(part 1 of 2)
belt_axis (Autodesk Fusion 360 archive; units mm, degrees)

design "assy_belt_axis" references "belt_idler", "HW_M5x40-FHCS", "HW_M3x50-SHCS", "carriage_front_generic", "circuit_mount_stepper_simple", "belt_motor_mount", "HW_M3-Washer", "FRM-Extrusion-VSlot-2020-350", "HW_M5x10-FHCS", "HW_M3x8-SHCS", "limit_mount", "HW_M3x16-SHCS", "lil_foot", "belt_clip"
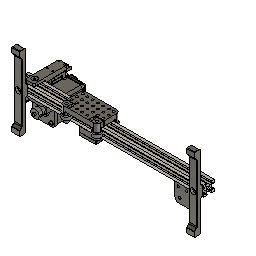
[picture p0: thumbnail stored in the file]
component_insert "Component Insert1"
joint "Assemble1" alignAngle -90 alignOffsetX 0 alignOffsetY 0 alignOffsetZ -6
component_insert "Component Insert2"
joint "Assemble2" alignAngle 0 alignOffsetX 0 alignOffsetY 0 alignOffsetZ -10
component_insert "Component Insert3"
joint "Assemble3" alignAngle 90 alignOffsetX 0 alignOffsetY 0 alignOffsetZ 0
component_insert "Component Insert4"
joint "Assemble4" alignAngle 0 alignOffsetX 0 alignOffsetY 25 alignOffsetZ 6
component_insert "Component Insert5"
joint "Assemble5" alignAngle 180 alignOffsetX 0 alignOffsetY -22 alignOffsetZ 6
component_insert "Component Insert6"
joint "Assemble6" alignAngle 270 alignOffsetX 0 alignOffsetY 21 alignOffsetZ 6
component_insert "Component Insert7"
joint "Assemble7" alignAngle 0 alignOffsetX 0 alignOffsetY 10 alignOffsetZ 6
component_insert "Component Insert8"
joint "Assemble8" alignAngle 0 alignOffsetX 0 alignOffsetY -10 alignOffsetZ 6
component_insert "Component Insert9"
joint "Assemble9" alignAngle 90 alignOffsetX 0 alignOffsetY 0 alignOffsetZ 0
component_insert "Component Insert10"
joint "Assemble10" alignAngle 180 alignOffsetX 0 alignOffsetY 0 alignOffsetZ 0
component_insert "Component Insert11"
component_insert "Component Insert12"
component_insert "Component Insert13"
component_insert "Component Insert14"
component_insert "Component Insert15"
component_insert "Component Insert16"
component_insert "Component Insert17"
component_insert "Component Insert18"
joint "Assemble11" alignAngle 90 alignOffsetX 0 alignOffsetY 0 alignOffsetZ 0
joint "Assemble12" alignAngle 90 alignOffsetX 0 alignOffsetY 0 alignOffsetZ 0
joint "Assemble13" alignAngle -90 alignOffsetX 0 alignOffsetY 0 alignOffsetZ 0
joint "Assemble14" alignAngle 90 alignOffsetX 0 alignOffsetY 0 alignOffsetZ 0
joint "Assemble15" alignAngle -90 alignOffsetX 0 alignOffsetY 0 alignOffsetZ 0
joint "Assemble16" alignAngle -90 alignOffsetX 0 alignOffsetY 0 alignOffsetZ 0
joint "Assemble17" alignAngle 90 alignOffsetX 0 alignOffsetY 0 alignOffsetZ 0
joint "Assemble18" alignAngle 90 alignOffsetX 0 alignOffsetY 0 alignOffsetZ 0
component_insert "Component Insert19"
component_insert "Component Insert20"
joint "Assemble19" alignAngle 90 alignOffsetX 0 alignOffsetY 0 alignOffsetZ 0
joint "Assemble20" alignAngle -90 alignOffsetX 0 alignOffsetY 0 alignOffsetZ 0
component_insert "Component Insert21"
component_insert "Component Insert22"
joint "Assemble21" alignAngle -90 alignOffsetX 0 alignOffsetY 0 alignOffsetZ 0
joint "Assemble22" alignAngle -90 alignOffsetX 0 alignOffsetY 0 alignOffsetZ 0
component_insert "Component Insert23"
joint "Assemble23" alignAngle 180 alignOffsetX 0 alignOffsetY 0 alignOffsetZ 0
component_insert "Component Insert24"
component_insert "Component Insert25"
component_insert "Component Insert26"
component_insert "Component Insert27"
component_insert "Component Insert28"
component_insert "Component Insert29"
component_insert "Component Insert30"
component_insert "Component Insert31"
joint "Assemble24" alignAngle 90 alignOffsetX 0 alignOffsetY 0 alignOffsetZ 0
joint "Assemble25" alignAngle 90 alignOffsetX 0 alignOffsetY 0 alignOffsetZ 0
joint "Assemble26" alignAngle 90 alignOffsetX 0 alignOffsetY 0 alignOffsetZ 0
joint "Assemble27" alignAngle 90 alignOffsetX 0 alignOffsetY 0 alignOffsetZ 0
joint "Assemble28" alignAngle 0 alignOffsetX 0 alignOffsetY 0 alignOffsetZ 0
joint "Assemble29" alignAngle 0 alignOffsetX 0 alignOffsetY 0 alignOffsetZ 0
joint "Assemble30" alignAngle 0 alignOffsetX 0 alignOffsetY 0 alignOffsetZ 0
joint "Assemble31" alignAngle 0 alignOffsetX 0 alignOffsetY 0 alignOffsetZ 0
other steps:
joint_origin "JointOrigin1"
joint_origin "JointOrigin2"

design "PP_TRNS_Mini-V-Wheel"
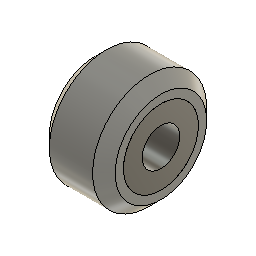
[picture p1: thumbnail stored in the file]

design "PP_BRNG_625F-5x16x5"
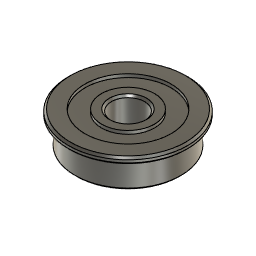
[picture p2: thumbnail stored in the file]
sketch "Sketch1" plane through (0, 0, 0) normal (0, 1, 0) x axis (1, 0, 0)
  line L1 (4, -2.5) -> (2.5, -2.5)
  line L2 (2.5, 2.5) -> (4, 2.5)
  line L3 (2.5, -2.5) -> (2.5, 2.5)
  line L4 (8, -2.5) -> (6.5, -2.5)
  line L5 (8, 2.5) -> (8, -2.5)
  line L6 (6.5, 2.5) -> (8, 2.5)
  line L7 (6.5, -2) -> (4, -2)
  line L8 (6.5, 2) -> (4, 2)
  line L9 (4, -2) -> (4, -2.5)
  line L10 (4, 2.5) -> (4, 2)
  line L11 (6.5, 2) -> (6.5, 2.5)
  line L12 (6.5, -2.5) -> (6.5, -2)
  line L13 (0, 0) -> (8, 0)
  line L14 (9, -2.5) -> (8, -2.5)
  line L15 (9, -1.5) -> (9, -2.5)
  line L16 (8, -1.5) -> (9, -1.5)
  point P11 (6.5, -2)
  point P12 (4, 2)
  point P14 (8, 0)
  point P1 (0, 0)
  point P15 (0, 0)
  point P16 (2.5, 0)
  point P6 (6.5, -2.5)
  point P19 (8, -1.5)
  point P3 (4, -2.5)
  point P10 (4, -2)
  point P7 (8, -2.5)
  point P8 (8, 2.5)
  point P2 (2.5, -2.5)
  point P17 (9, -2.5)
  point P18 (9, -1.5)
  horizontal L1
  vertical L9
  horizontal L2
  vertical L3
  horizontal L4
  vertical L5
  horizontal L6
  vertical L11
  coincident P11 L11
  perpendicular L7 L11
  coincident P12 L9
  perpendicular L8 L9
  collinear L9 L10
  collinear L11 L12
  midpoint L5 P14
  coincident P1 P15
  horizontal L13
  midpoint L3 P16
  coincident L13 P16
  equal L1 L4
  equal L9 L10
  coincident L1 P6
  perpendicular L5 L14
  perpendicular L4 L15
  coincident L5 P19
  perpendicular L5 L16
  dimension "d1" distance P1 L3 = 2.5 (= "( 5 / 2 ) * 1 mm")
  dimension "d2" distance P1 L5 = 8 (= "( 16 / 2 ) * 1 mm")
  dimension "d4" distance P3 P10 = 0.5
  dimension "d5" distance P7 P8 = 5
  dimension "d8" distance P2 P3 = 1.5
  dimension "d9" distance P17 P18 = 1
  dimension "d10" distance P1 P17 = 9 (= "( 18 / 2 ) * 1 mm")
revolve "Revolve1" sketch "Sketch1" AlongAngle 360
chamfer "Chamfer1" distance 0.3

design "HW_M5x10-FHCS"
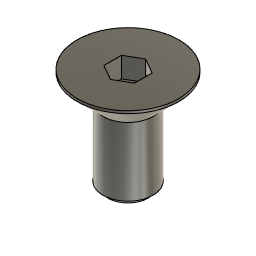
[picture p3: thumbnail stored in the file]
sketch "Sketch1" plane through (0, 0, 0) normal (0, 1, 0) x axis (1, 0, 0)
  line L1 (0, 10) -> (0, 0)
  line L2 (1.95, 10) -> (0, 10)
  line L3 (2.45, 9.5) -> (1.95, 10)
  line L4 (2.45, 2.8) -> (2.45, 9.5)
  line L5 (5, 0.25) -> (2.45, 2.8)
  line L6 (5, 0) -> (5, 0.25)
  line L7 (0, 0) -> (5, 0)
  point P1 (0, 0)
  point P2 (0, 0)
  point P9 (0, 0)
  point P3 (0, 10)
  point P4 (1.95, 10)
  point P8 (5, 0)
  point P7 (5, 0.25)
  coincident P1 P2
  vertical L1
  perpendicular L1 L2
  perpendicular L2 L4
  parallel L3 L5
  parallel L4 L6
  perpendicular L6 L7
  coincident P1 P9
  dimension "d1" distance P3 L4 = 2.45 (= "( 4.9 / 2 ) * 1 mm")
  dimension "d3" angle L2 L3 = 45
  dimension "d5" distance P4 L4 = 0.5
  dimension "d6" distance P2 P3 = 10
  dimension "d7" distance P8 P9 = 5 (= "( 10 / 2 ) * 1 mm")
  dimension "d9" distance P7 P8 = 0.25
revolve "Revolve1" sketch "Sketch1" AlongAngle 360
sketch "Sketch2" plane through (0, 0, 0) normal (0, 0, 1) x axis (-1, 0, 0)
  line L1 (0, -1.7321) -> (-1.5, -0.866)
  line L2 (1.5, -0.866) -> (0, -1.7321)
  line L3 (1.5, 0.866) -> (1.5, -0.866)
  line L4 (0, 1.7321) -> (1.5, 0.866)
  line L5 (-1.5, 0.866) -> (0, 1.7321)
  line L6 (-1.5, -0.866) -> (-1.5, 0.866)
  circle C1 centre (0, 0) radius 5
  point P1 (0, 0)
  point P9 (0, 0)
  coincident P1 P9
  vertical L6
  dimension "d12" distance L3 L6 = 3
extrude "Extrude1" cut sketch "Sketch2" profile of L1 L2 L3 L4 L5 L6 against normal blind 2

design "lil_foot"
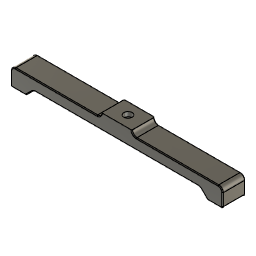
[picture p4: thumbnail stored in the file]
sketch "Sketch1" plane through (0, 0, 0) normal (0, 1, 0) x axis (1, 0, 0)
  line L1 (0, 0) -> (-10, 0)
  line L2 (-10, 3) -> (-10, 0)
  line L3 (-70, 3) -> (-10, 3)
  line L4 (-70, 15) -> (-70, 3)
  line L5 (-60, 15) -> (-70, 15)
  line L6 (-55, 10) -> (-60, 15)
  line L7 (0, 10) -> (-55, 10)
  line L8 (0, 0) -> (0, 10)
  line L9 (0, 0) -> (10, 0)
  line L10 (10, 3) -> (10, 0)
  line L11 (70, 3) -> (10, 3)
  line L12 (70, 15) -> (70, 3)
  line L13 (60, 15) -> (70, 15)
  line L14 (55, 10) -> (60, 15)
  line L15 (0, 10) -> (55, 10)
  point P1 (0, 0)
  point P9 (0, 0)
  point P10 (0, 0)
  point P2 (-10, 0)
  point P11 (10, 0)
  point P3 (-10, 3)
  point P13 (10, 3)
  point P4 (-70, 3)
  point P14 (70, 3)
  point P5 (-70, 15)
  point P15 (70, 15)
  point P6 (-60, 15)
  point P16 (60, 15)
  point P7 (-55, 10)
  point P17 (55, 10)
  point P8 (0, 10)
  point P18 (0, 10)
  point P12 (0, 0)
  horizontal L1
  perpendicular L1 L2
  perpendicular L2 L3
  perpendicular L3 L4
  perpendicular L4 L5
  perpendicular L4 L7
  perpendicular L7 L8
  coincident P1 P9
  coincident L8 P10
  coincident P1 P10
  symmetric P2 L8 P11
  symmetric P3 L8 P13
  symmetric P4 L8 P14
  symmetric P5 L8 P15
  symmetric P6 L8 P16
  symmetric P7 L8 P17
  symmetric P8 L8 P18
  symmetric L8 P10 P12
  dimension "d2" distance P2 P10 = 10
  dimension "d4" angle L6 L7 = 45
  dimension "d5" distance P5 P6 = 10
  dimension "d6" distance P6 P7 = 5
  dimension "d8" distance P5 P8 = 70 (= "( 140 / 2 ) * 1 mm")
  dimension "d9" distance P2 P3 = 3
  dimension "d11" distance P2 P5 = 15
  dimension "d12" distance P1 P8 = 10
extrude "Extrude1" new body sketch "Sketch1" profile of L1 L2 L3 L4 L5 L6 L7 L9 L10 L11 L12 L13 L14 L15 along normal blind 15
sketch "Sketch2" plane through (0, 0, 0) normal (0, 0, 1) x axis (-1, 0, 0)
  line L1 (-10, 0) -> (10, 0)
  line L2 (-10, -15) -> (-10, 0)
  line L3 (10, -15) -> (-10, -15)
  line L4 (10, 0) -> (10, -15)
  line L5 (0, -15) -> (0, 0)
  circle C1 centre (0, -7.5) radius 2.75
  circle C2 centre (0, -7.5) radius 5.25
  point P1 (0, 0)
  point P6 (0, 0)
  point P7 (0, -15)
  point P8 (0, -7.5)
  coincident P1 P6
  midpoint L3 P7
  midpoint L5 P8
  concentric C1 C2
  dimension "d15" diameter C2 = 10.5
  dimension "d16" diameter C1 = 5.5
extrude "Extrude2" cut sketch "Sketch2" profile of C1 to an object
extrude "Extrude3" cut sketch "Sketch2" profile of L2 L4 C1 C2 no distance stored from offset -5.5
chamfer "Chamfer1" distance 2.5
fillet "Fillet1" radius 3
fillet "Fillet2" radius 1
chamfer "Chamfer2" distance 0.5
named bodies: "lil_foot"

design "HW_M5-Washer"
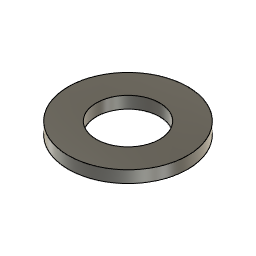
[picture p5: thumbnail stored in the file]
sketch "Sketch1" plane through (0, 0, 0) normal (0, 1, 0) x axis (1, 0, 0)
  line L1 (5, 0) -> (2.65, 0)
  line L2 (5, -1) -> (5, 0)
  line L3 (2.65, -1) -> (5, -1)
  line L4 (2.65, 0) -> (2.65, -1)
  point P1 (0, 0)
  point P2 (2.65, 0)
  point P5 (2.65, -1)
  horizontal L1
  vertical L2
  horizontal L3
  vertical L4
  coincident P1 L1
  dimension "d1" distance P2 P5 = 1
  dimension "d2" distance P1 L4 = 2.65 (= "( 5.3 / 2 ) * 1 mm")
  dimension "d3" distance P1 L2 = 5 (= "( 10 / 2 ) * 1 mm")
revolve "Revolve1" sketch "Sketch1" AlongAngle 360

design "belt_motor_mount" references "PP_ACTU_N17-Stepper", "PP_TRNS_GT2-Pulley-20T-6mm"
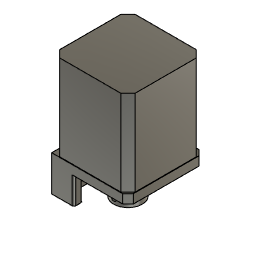
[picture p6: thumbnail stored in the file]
sketch "Sketch1" plane through (0, 0, 0) normal (0, 0, 1) x axis (1, 0, 0)
  line L1 (0.2162, 21.15) -> (42.5162, 21.15)
  line L2 (0.2162, -21.15) -> (0.2162, 21.15)
  line L3 (42.5162, -21.15) -> (0.2162, -21.15)
  line L4 (42.5162, 21.15) -> (42.5162, -21.15)
  line L5 (0.2162, -21.15) -> (42.5162, 21.15)
  line L6 (42.5162, -21.15) -> (0.2162, 21.15)
  line L7 (0, 0) -> (21.3662, 0)
  line L8 (36.8662, 15.5) -> (5.8662, 15.5)
  line L9 (36.8662, -15.5) -> (36.8662, 15.5)
  line L10 (5.8662, -15.5) -> (36.8662, -15.5)
  line L11 (5.8662, 15.5) -> (5.8662, -15.5)
  line L12 (5, -12.1089) -> (5, 12.1089)
  line L13 (12.5, -16.4) -> (9.2485, -16.4)
  line L14 (12.5, -21.4) -> (12.5, -16.4)
  line L15 (0, 21.4) -> (0, -21.4)
  line L16 (42.7662, 21.4) -> (0, 21.4)
  line L17 (42.7662, -21.4) -> (42.7662, 21.4)
  line L18 (0, -21.4) -> (42.7662, -21.4)
  line L19 (12.5, 16.4) -> (9.2485, 16.4)
  line L20 (12.5, 21.4) -> (12.5, 16.4)
  circle C1 centre (21.3662, 0) radius 6.3662
  circle C2 centre (36.8662, 15.5) radius 1.75
  circle C3 centre (36.8662, -15.5) radius 1.75
  circle C4 centre (5.8662, -15.5) radius 1.75
  circle C5 centre (5.8662, 15.5) radius 1.75
  circle C6 centre (21.3662, 0) radius 11.05
  circle C7 centre (5.8662, -15.5) radius 3.5
  circle C8 centre (5.8662, 15.5) radius 3.5
  point P6 (21.3662, 0)
  point P7 (21.3662, 0)
  point P8 (21.3662, 0)
  point P1 (0, 0)
  point P9 (0, 0)
  point P10 (15, 0)
  point P13 (36.8662, -15.5)
  point P11 (5.8662, 15.5)
  point P12 (36.8662, 15.5)
  point P19 (21.3662, 0)
  point P15 (36.8662, 15.5)
  point P16 (36.8662, -15.5)
  point P14 (5.8662, -15.5)
  point P17 (5.8662, -15.5)
  point P18 (5.8662, 15.5)
  point P20 (5, 12.1089)
  point P21 (5, -12.1089)
  point P24 (9.2485, -16.4)
  point P27 (0, -21.4)
  point P31 (0, -21.4)
  point P26 (12.5, -21.4)
  point P32 (9.2485, 16.4)
  point P34 (12.5, 21.4)
  point P25 (12.5, -16.4)
  point P2 (42.5162, 21.15)
  point P5 (42.5162, -21.15)
  point P3 (0.2162, 21.15)
  point P29 (42.7662, 21.4)
  horizontal L1
  perpendicular L1 L2
  parallel L1 L3
  parallel L2 L4
  coincident L5 P6
  coincident L6 P6
  equal L1 L2
  coincident P6 P7
  coincident P6 P8
  coincident P1 P9
  horizontal L7
  coincident C1 P10
  coincident L7 P10
  horizontal L8
  vertical L9
  horizontal L10
  vertical L11
  coincident L6 P13
  coincident L6 P11
  coincident L5 P12
  equal C4 C5
  equal C3 C5
  equal C2 C3
  coincident P6 P19
  coincident P12 P15
  coincident P13 P16
  coincident P14 P17
  coincident P11 P18
  vertical L12
  concentric C4 C7
  concentric C5 C8
  equal C7 C8
  coincident P20 C8
  coincident P21 C7
  coincident C7 P24
  parallel L3 L13
  perpendicular L3 L14
  perpendicular L1 L15
  midpoint P1 L15
  perpendicular L15 L16
  perpendicular L16 L17
  perpendicular L17 L18
  coincident P27 P31
  coincident P26 L18
  coincident C8 P32
  parallel L8 L19
  coincident L16 P34
  perpendicular L16 L20
  coincident P25 L20
  equal L14 L20
  dimension "d1" diameter C1 = 12.7324 (= "( 20 * 2 / PI ) * 1 mm")
  dimension "d2" distance P1 P10 = 15
  dimension "d3" distance P2 P5 = 42.3
  dimension "d4" diameter C2 = 3.5
  dimension "d5" diameter C6 = 22.1
  dimension "d6" distance P12 P13 = 31
  dimension "d7" distance P1 L12 = 5
  dimension "d8" diameter C8 = 7
  dimension "d9" distance P3 L16 = 0.25
  dimension "d10" distance L4 P29 = 0.25
  dimension "d11" distance P10 L14 = 2.5
  dimension "d12" distance L13 P26 = 5
extrude "Extrude1" new body sketch "Sketch1" profile of C2 C3 C4 C5 C6 L12 C7 C8 L13 L14 L15 L16 L17 L18 L19 L20 along normal blind 5 bodies "belt_motor_mount"
extrude "Extrude2" add sketch "Sketch1" profile of L12 C7 C8 L13 L14 L15 L16 L18 L19 L20 against normal blind 15
sketch "Sketch2" plane through (0, 0, 0) normal (-1, 0, 0) x axis (0, -1, 0)
  line L1 (21.4, 5) -> (21.4, -15)
  line L2 (-21.4, 5) -> (21.4, 5)
  line L3 (-21.4, -15) -> (-21.4, 5)
  line L4 (21.4, -15) -> (-21.4, -15)
  line L5 (-21.4, -5) -> (21.4, -5)
  circle C1 centre (-7.4, -5) radius 2.75
  circle C2 centre (-7.4, -5) radius 5
  circle C3 centre (7.4, -5) radius 2.75
  circle C4 centre (7.4, -5) radius 5
  point P6 (21.4, -5)
  point P7 (-21.4, -5)
  point P8 (-7.4, -5)
  point P10 (7.4, -5)
  point P4 (-21.4, 5)
  point P9 (-7.4, -5)
  point P3 (21.4, 5)
  point P11 (7.4, -5)
  midpoint L1 P6
  midpoint L3 P7
  coincident L5 P8
  concentric C1 C2
  coincident L5 P10
  concentric C3 C4
  equal C2 C4
  equal C1 C3
  dimension "d17" distance P4 P9 = 14
  dimension "d18" distance P3 P11 = 14 (= "d17")
  dimension "d19" diameter C1 = 5.5
  dimension "d20" diameter C2 = 10
extrude "Extrude3" cut sketch "Sketch2" profile of C1 C3 no distance stored
chamfer "Chamfer1" distance 2.5
chamfer "Chamfer2" distance 3
fillet "Fillet1" radius 1
fillet "Fillet2" radius 3
fillet "Fillet3" radius 1
component_insert "Component Insert1"
joint "Assemble1" alignAngle 0 alignOffsetX 0 alignOffsetY 0 alignOffsetZ 0
component_insert "Component Insert2"
joint "Assemble2" alignAngle 0 alignOffsetX 0 alignOffsetY 0 alignOffsetZ -3
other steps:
joint_origin "JointOrigin1"
named bodies: "belt_motor_mount"

design "FRM-Extrusion-VSlot-2020-350"
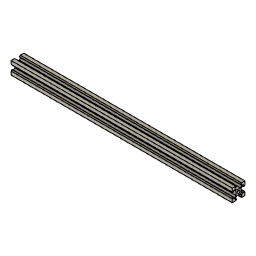
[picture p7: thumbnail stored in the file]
parameter "d90" = 4
parameter "d92" = 0.75 (= "( 1.5 / 2 ) * 1 mm")
sketch "Sketch4" plane through (0, 0, 0) normal (1, 0, 0) x axis (0, 1, 0)
  line L1 (20, 0) -> (0, 0)
  line L2 (20, 20) -> (20, 0)
  line L3 (0, 20) -> (20, 20)
  line L4 (0, 0) -> (0, 20)
  line L5 (10, 0) -> (10, 20)
  line L6 (0, 10) -> (20, 10)
  line L7 (15.5, 18.2) -> (13.125, 18.2)
  line L8 (12.9393, 14) -> (15.5, 16.5607)
  line L9 (10, 14) -> (12.9393, 14)
  line L10 (20, 20) -> (10, 10)
  line L11 (13.125, 18.545) -> (13.125, 18.2)
  line L12 (14.58, 20) -> (13.125, 18.545)
  line L13 (15.5, 16.5607) -> (15.5, 18.2)
  line L14 (20, 14.58) -> (18.545, 13.125)
  line L15 (18.545, 13.125) -> (18.2, 13.125)
  line L16 (16.5607, 15.5) -> (18.2, 15.5)
  line L17 (14, 12.9393) -> (16.5607, 15.5)
  line L18 (14, 10) -> (14, 12.9393)
  line L19 (18.2, 15.5) -> (18.2, 13.125)
  line L20 (5.42, 20) -> (6.875, 18.545)
  line L21 (6.875, 18.545) -> (6.875, 18.2)
  line L22 (4.5, 18.2) -> (6.875, 18.2)
  line L23 (4.5, 16.5607) -> (4.5, 18.2)
  line L24 (10, 14) -> (7.0607, 14)
  line L25 (7.0607, 14) -> (4.5, 16.5607)
  line L26 (0, 14.58) -> (1.455, 13.125)
  line L27 (1.455, 13.125) -> (1.8, 13.125)
  line L28 (1.8, 15.5) -> (1.8, 13.125)
  line L29 (3.4393, 15.5) -> (1.8, 15.5)
  line L30 (6, 10) -> (6, 12.9393)
  line L31 (6, 12.9393) -> (3.4393, 15.5)
  line L32 (5.42, 0) -> (6.875, 1.455)
  line L33 (6.875, 1.455) -> (6.875, 1.8)
  line L34 (4.5, 1.8) -> (6.875, 1.8)
  line L35 (4.5, 3.4393) -> (4.5, 1.8)
  line L36 (7.0607, 6) -> (4.5, 3.4393)
  line L37 (10, 6) -> (7.0607, 6)
  line L38 (14.58, 0) -> (13.125, 1.455)
  line L39 (13.125, 1.455) -> (13.125, 1.8)
  line L40 (15.5, 1.8) -> (13.125, 1.8)
  line L41 (15.5, 3.4393) -> (15.5, 1.8)
  line L42 (12.9393, 6) -> (15.5, 3.4393)
  line L43 (10, 6) -> (12.9393, 6)
  line L44 (0, 5.42) -> (1.455, 6.875)
  line L45 (1.455, 6.875) -> (1.8, 6.875)
  line L46 (1.8, 4.5) -> (1.8, 6.875)
  line L47 (3.4393, 4.5) -> (1.8, 4.5)
  line L48 (6, 10) -> (6, 7.0607)
  line L49 (6, 7.0607) -> (3.4393, 4.5)
  line L50 (20, 5.42) -> (18.545, 6.875)
  line L51 (18.545, 6.875) -> (18.2, 6.875)
  line L52 (18.2, 4.5) -> (18.2, 6.875)
  line L53 (16.5607, 4.5) -> (18.2, 4.5)
  line L54 (14, 10) -> (14, 7.0607)
  line L55 (14, 7.0607) -> (16.5607, 4.5)
  circle C1 centre (10, 10) radius 2.2
  point P1 (0, 0)
  point P2 (0, 0)
  point P6 (10, 20)
  point P7 (10, 0)
  point P8 (20, 10)
  point P9 (0, 10)
  point P12 (10, 14)
  point P13 (10, 10)
  point P14 (10, 10)
  point P16 (14.58, 20)
  point P10 (13.125, 18.2)
  point P21 (18.2, 13.125)
  point P11 (12.9393, 14)
  point P24 (14, 12.9393)
  point P25 (14, 10)
  point P15 (13.125, 18.545)
  point P19 (18.545, 13.125)
  point P20 (20, 14.58)
  point P17 (15.5, 18.2)
  point P22 (18.2, 15.5)
  point P18 (15.5, 16.5607)
  point P23 (16.5607, 15.5)
  point P28 (6.875, 18.2)
  point P31 (7.0607, 14)
  point P32 (10, 14)
  point P26 (6.875, 18.545)
  point P27 (5.42, 20)
  point P29 (4.5, 18.2)
  point P30 (4.5, 16.5607)
  point P33 (1.455, 13.125)
  point P34 (0, 14.58)
  point P35 (1.8, 13.125)
  point P36 (1.8, 15.5)
  point P37 (3.4393, 15.5)
  point P38 (6, 12.9393)
  point P39 (6, 10)
  point P49 (13.125, 1.8)
  point P52 (12.9393, 6)
  point P53 (10, 6)
  point P47 (13.125, 1.455)
  point P48 (14.58, 0)
  point P50 (15.5, 1.8)
  point P51 (15.5, 3.4393)
  point P61 (18.545, 6.875)
  point P62 (20, 5.42)
  point P63 (18.2, 6.875)
  point P64 (18.2, 4.5)
  point P65 (16.5607, 4.5)
  point P66 (14, 7.0607)
  point P67 (14, 10)
  point P40 (6.875, 1.455)
  point P41 (5.42, 0)
  point P42 (6.875, 1.8)
  point P43 (4.5, 1.8)
  point P44 (4.5, 3.4393)
  point P45 (7.0607, 6)
  point P46 (10, 6)
  point P54 (1.455, 6.875)
  point P55 (0, 5.42)
  point P56 (1.8, 6.875)
  point P57 (1.8, 4.5)
  point P58 (3.4393, 4.5)
  point P59 (6, 7.0607)
  point P60 (6, 10)
  point P3 (20, 0)
  point P4 (20, 20)
  horizontal L1
  vertical L2
  horizontal L3
  vertical L4
  coincident P1 P2
  equal L1 L4
  midpoint L3 P6
  midpoint L1 P7
  midpoint L2 P8
  midpoint L4 P9
  coincident L5 P12
  perpendicular L5 L9
  midpoint L5 P13
  coincident P13 P14
  parallel L8 L10
  perpendicular L7 L11
  coincident L3 P16
  parallel L10 L12
  perpendicular L7 L13
  horizontal L7
  symmetric P10 L10 P21
  symmetric P11 L10 P24
  symmetric P12 L10 P25
  symmetric L10 P15 P19
  symmetric L10 P16 P20
  symmetric L10 P17 P22
  symmetric L10 P18 P23
  symmetric L5 P10 P28
  symmetric L5 P11 P31
  symmetric L5 P12 P32
  symmetric L5 P15 P26
  symmetric L5 P16 P27
  symmetric L5 P17 P29
  symmetric L5 P18 P30
  symmetric L5 P19 P33
  symmetric L5 P20 P34
  symmetric L5 P21 P35
  symmetric L5 P22 P36
  symmetric L5 P23 P37
  symmetric L5 P24 P38
  symmetric L5 P25 P39
  symmetric L6 P10 P49
  symmetric L6 P11 P52
  symmetric L6 P12 P53
  symmetric L6 P15 P47
  symmetric L6 P16 P48
  symmetric L6 P17 P50
  symmetric L6 P18 P51
  symmetric L6 P19 P61
  symmetric L6 P20 P62
  symmetric L6 P21 P63
  symmetric L6 P22 P64
  symmetric L6 P23 P65
  symmetric L6 P24 P66
  symmetric L6 P25 P67
  symmetric L6 P26 P40
  symmetric L6 P27 P41
  symmetric L6 P28 P42
  symmetric L6 P29 P43
  symmetric L6 P30 P44
  symmetric L6 P31 P45
  symmetric L6 P32 P46
  symmetric L6 P33 P54
  symmetric L6 P34 P55
  symmetric L6 P35 P56
  symmetric L6 P36 P57
  symmetric L6 P37 P58
  symmetric L6 P38 P59
  symmetric L6 P39 P60
  dimension "d177" distance P2 P3 = 20
  dimension "d178" diameter C1 = 4.4
  dimension "d181" distance P4 L8 = 0.75 (= "( 1.5 / 2 ) * 1 mm")
  dimension "d182" distance L9 P13 = 4
  dimension "d215" distance P6 L13 = 5.5 (= "( 11 / 2 ) * 1 mm")
  dimension "d216" distance P6 P10 = 3.125 (= "( 6.25 / 2 ) * 1 mm")
  dimension "d217" distance P6 P16 = 4.58 (= "( 9.16 / 2 ) * 1 mm")
  dimension "d219" distance P4 P17 = 1.8
  dimension "d220" distance P10 L9 = 4.2
  dimension "d32" distance = 3 (= "( 6 / 2 ) * 1 mm")
  dimension "d33" distance = 3 (= "d32")
  dimension "d34" distance = 3 (= "d33")
  dimension "d35" distance = 3 (= "d32")
  dimension "d43" distance = 2
  dimension "d44" distance = 2 (= "d43")
extrude "Extrude3" new body sketch "Sketch4" profile of L1 L2 L3 L4 L7 L8 L9 C1 L11 L12 L13 L14 L15 L16 L17 L18 L19 L20 L21 L22 L23 L24 L25 L26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 along normal blind 350
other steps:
step "Extrude" AlongDistance -1.5 TaperAngle 0
step "Fillet" ChordLen 3
step "Chamfer5" Distance 0.5
step "Chamfer6" Distance 1

design "HW_M3x8-SHCS"
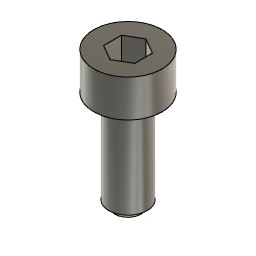
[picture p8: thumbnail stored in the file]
sketch "Sketch1" plane through (0, 0, 0) normal (0, 1, 0) x axis (1, 0, 0)
  line L1 (0, 8) -> (0, -3)
  line L2 (1.05, 8) -> (0, 8)
  line L3 (1.55, 7.5) -> (1.05, 8)
  line L4 (1.55, 0) -> (1.55, 7.5)
  line L5 (2.75, 0) -> (1.55, 0)
  line L6 (2.75, -3) -> (2.75, 0)
  line L7 (0, -3) -> (2.75, -3)
  point P1 (0, 0)
  point P4 (1.05, 8)
  point P5 (1.55, 7.5)
  point P3 (0, 8)
  point P7 (2.75, 0)
  point P8 (2.75, -3)
  point P2 (0, -3)
  vertical L1
  perpendicular L1 L2
  perpendicular L2 L4
  perpendicular L4 L5
  perpendicular L5 L6
  horizontal L7
  coincident P1 L1
  coincident P1 L5
  dimension "d1" distance P1 L2 = 8
  dimension "d2" angle L2 L3 = 45
  dimension "d3" distance P4 P5 = 0.5
  dimension "d4" distance P3 L4 = 1.55 (= "( 3.1 / 2 ) * 1 mm")
  dimension "d5" distance P7 P8 = 3
  dimension "d6" distance P2 P8 = 2.75 (= "( 5.5 / 2 ) * 1 mm")
revolve "Revolve1" sketch "Sketch1" AlongAngle 360
sketch "Sketch2" plane through (0, 0, 3) normal (0, 0, 1) x axis (-1, 0, 0)
  line L1 (0, -1.4434) -> (-1.25, -0.7217)
  line L2 (1.25, -0.7217) -> (0, -1.4434)
  line L3 (1.25, 0.7217) -> (1.25, -0.7217)
  line L4 (0, 1.4434) -> (1.25, 0.7217)
  line L5 (-1.25, 0.7217) -> (0, 1.4434)
  line L6 (-1.25, -0.7217) -> (-1.25, 0.7217)
  circle C1 centre (0, 0) radius 2.75
  point P1 (0, 0)
  point P9 (0, 0)
  point P5 (1.25, -0.7217)
  coincident P1 P9
  vertical L6
  dimension "d8" distance P5 L6 = 2.5
extrude "Extrude1" cut sketch "Sketch2" profile of L1 L2 L3 L4 L5 L6 against normal blind 2

design "carriage_front_generic" references "HW_M5x20-SHCS", "PP_TRNS_Mini-V-Wheel"
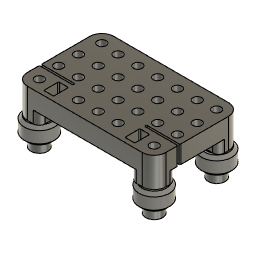
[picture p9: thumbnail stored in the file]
sketch "Sketch1" plane through (0, 0, 0) normal (0, 0, 1) x axis (1, 0, 0)
  line L1 (0, -21.8) -> (0, 21.8)
  line L2 (-18, -12.01) -> (-23, -12.01)
  line L3 (-18, -19.54) -> (-18, -12.01)
  line L4 (-23, -19.54) -> (-18, -19.54)
  line L5 (-23, -12.01) -> (-23, -19.54)
  line L6 (-1.8225, 21.8) -> (0, 21.8)
  line L7 (-35, 21.8) -> (-1.8225, 21.8)
  line L8 (-35, -8.75) -> (-35, 21.8)
  line L9 (-18, -8.75) -> (-35, -8.75)
  line L10 (-18, -9.75) -> (-18, -8.75)
  line L11 (-35, -9.75) -> (-18, -9.75)
  line L12 (-35, -21.8) -> (-35, -9.75)
  line L13 (0, -21.8) -> (-35, -21.8)
  line L14 (-29, 15.8) -> (-29, -15.75)
  line L15 (0, 10) -> (-35, 10)
  line L16 (0, -10) -> (-35, -10)
  line L17 (-23, -10.75) -> (-35, -10.75)
  line L18 (-23, -12.01) -> (-23, -10.75)
  line L19 (-23, -21.8) -> (-23, -19.54)
  line L20 (-23, 10.75) -> (-35, 10.75)
  line L21 (-23, 21.8) -> (-23, 10.75)
  circle C1 centre (-29, 15.8) radius 2.2
  circle C2 centre (-29, -15.75) radius 2.2
  circle C3 centre (-29, -15.75) radius 5
  circle C4 centre (-29, 15.8) radius 5
  circle C5 centre (-29, 15.8) radius 3.7
  circle C6 centre (-29, -15.75) radius 3.7
  circle C7 centre (0, 15) radius 2.2
  point P1 (0, 0)
  point P3 (0, -21.8)
  point P19 (0, -21.8)
  point P5 (-29, -15.75)
  point P20 (-29, -15.75)
  point P11 (-29, 15.8)
  point P21 (-29, 15.8)
  point P7 (-18, -12.01)
  point P22 (-35, 10)
  point P23 (0, 10)
  point P24 (-35, -10)
  point P25 (0, -10)
  point P26 (-35, -10.75)
  point P6 (-23, -12.01)
  point P28 (-23, -12.01)
  point P29 (-23, -21.8)
  point P30 (-35, 10.75)
  point P32 (-23, 21.8)
  point P35 (0, 15)
  point P4 (-29, 15.8)
  point P13 (-35, 21.8)
  point P10 (-29, -15.75)
  point P2 (0, 21.8)
  point P15 (-18, -8.75)
  point P16 (-18, -9.75)
  vertical L1
  coincident P1 L1
  equal C1 C2
  horizontal L2
  vertical L3
  horizontal L4
  vertical L5
  concentric C2 C3
  concentric C1 C4
  equal C3 C4
  perpendicular L1 L6
  perpendicular L1 L7
  perpendicular L7 L8
  perpendicular L1 L9
  perpendicular L9 L10
  perpendicular L10 L11
  perpendicular L9 L12
  perpendicular L12 L13
  coincident P3 P19
  midpoint P1 L1
  coincident P5 P20
  coincident P11 P21
  vertical L14
  coincident P7 L10
  coincident L8 P22
  coincident L1 P23
  perpendicular L1 L15
  coincident L12 P24
  coincident L1 P25
  perpendicular L1 L16
  coincident L12 P26
  perpendicular L14 L17
  perpendicular L17 L18
  coincident P6 P28
  coincident L13 P29
  perpendicular L13 L19
  coincident L8 P30
  perpendicular L14 L20
  coincident L7 P32
  perpendicular L7 L21
  coincident P28 L21
  concentric C1 C5
  concentric C3 C6
  equal C5 C6
  coincident L1 P35
  dimension "d1" distance P1 P4 = 15.8
  dimension "d2" distance P1 P5 = 15.75 (= "d1 - 0.05 mm")
  dimension "d3" diameter C1 = 4.4
  dimension "d4" diameter C4 = 10
  dimension "d7" distance P4 P13 = 6
  dimension "d8" distance P4 P13 = 6
  dimension "d9" distance P10 L11 = 6
  dimension "d10" distance P10 L12 = 6
  dimension "d11" distance P2 P13 = 35
  dimension "d12" distance P15 P16 = 1
  dimension "d13" distance L5 P10 = 6
  dimension "d14" distance L2 L11 = 2.26
  dimension "d15" distance L4 L13 = 2.26 (= "d14")
  dimension "d16" distance P6 P7 = 5
  dimension "d17" distance P1 L15 = 10
  dimension "d18" distance P1 P25 = 10
  dimension "d19" distance P1 L17 = 10.75
  dimension "d20" distance P1 P30 = 10.75 (= "d19")
  dimension "d28" distance C1 C5 = 1.5
  dimension "d73" diameter C7 = 4.4
  dimension "d76" distance P1 P35 = 15
extrude "Extrude1" new body sketch "Sketch1" profile of L1 C1 C2 L2 L3 L4 L5 L6 L7 L8 L9 L10 L11 L12 L13 L17 L18 L19 L20 L21 blind 9 from offset 11 bodies "carriage_front_generic"
extrude "Extrude2" add sketch "Sketch1" profile of C1 C2 L5 L7 L8 L12 L13 L17 L18 L19 L20 L21 to an object from offset 4.4 (= "( 8.8 / 2 ) * 1 mm")
extrude "Extrude3" sketch "Sketch1" profile of L5 L7 L8 L12 L13 L17 L18 L19 L20 L21 C5 C6 blind 0.6
fillet "Fillet1" radius 0.5
fillet "Fillet2" radius 6
fillet "Fillet3" radius 3
extrude "Extrude4" cut sketch "Sketch1" profile of L1 C7 no distance stored
chamfer "Chamfer3" distance 1.5 distance 0.5
rectangular_pattern "R-Pattern1" uSpaceDistance 10 vSpaceDistance 10
mirror "Mirror1" mirrorStitchTolerance 0.1
component_insert "Component Insert2"
component_insert "Component Insert3"
component_insert "Component Insert4"
component_insert "Component Insert5"
joint "Assemble1" alignAngle 0 alignOffsetX 0 alignOffsetY 0 alignOffsetZ 0
joint "Assemble2" alignAngle 0 alignOffsetX 0 alignOffsetY 0 alignOffsetZ 0
joint "Assemble3" alignAngle 180 alignOffsetX 0 alignOffsetY 0 alignOffsetZ 0
joint "Assemble4" alignAngle 180 alignOffsetX 0 alignOffsetY 0 alignOffsetZ 0
component_insert "Component Insert11"
component_insert "Component Insert12"
component_insert "Component Insert13"
component_insert "Component Insert14"
joint "Assemble9" alignAngle 180 alignOffsetX 0 alignOffsetY 0 alignOffsetZ 0
joint "Assemble10" alignAngle 0 alignOffsetX 0 alignOffsetY 0 alignOffsetZ 0
joint "Assemble11" alignAngle 180 alignOffsetX 0 alignOffsetY 0 alignOffsetZ 0
joint "Assemble12" alignAngle 0 alignOffsetX 0 alignOffsetY 0 alignOffsetZ 0
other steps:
joint_origin "JointOrigin1"
joint_origin "JointOrigin2"
joint_origin "JointOrigin4"
joint_origin "JointOrigin5"
named bodies: "carriage_front_generic"

design "HW_M5x40-FHCS"
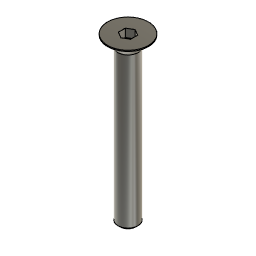
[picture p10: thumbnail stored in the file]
sketch "Sketch1" plane through (0, 0, 0) normal (0, 1, 0) x axis (1, 0, 0)
  line L1 (0, 40) -> (0, 0)
  line L2 (1.95, 40) -> (0, 40)
  line L3 (2.45, 39.5) -> (1.95, 40)
  line L4 (2.45, 2.8) -> (2.45, 39.5)
  line L5 (5, 0.25) -> (2.45, 2.8)
  line L6 (5, 0) -> (5, 0.25)
  line L7 (0, 0) -> (5, 0)
  point P1 (0, 0)
  point P2 (0, 0)
  point P9 (0, 0)
  point P3 (0, 40)
  point P4 (1.95, 40)
  point P8 (5, 0)
  point P7 (5, 0.25)
  coincident P1 P2
  vertical L1
  perpendicular L1 L2
  perpendicular L2 L4
  parallel L3 L5
  parallel L4 L6
  perpendicular L6 L7
  coincident P1 P9
  dimension "d1" distance P3 L4 = 2.45 (= "( 4.9 / 2 ) * 1 mm")
  dimension "d3" angle L2 L3 = 45
  dimension "d5" distance P4 L4 = 0.5
  dimension "d6" distance P2 P3 = 40
  dimension "d7" distance P8 P9 = 5 (= "( 10 / 2 ) * 1 mm")
  dimension "d9" distance P7 P8 = 0.25
revolve "Revolve1" sketch "Sketch1" AlongAngle 360
sketch "Sketch2" plane through (0, 0, 0) normal (0, 0, 1) x axis (-1, 0, 0)
  line L1 (0, -1.7321) -> (-1.5, -0.866)
  line L2 (1.5, -0.866) -> (0, -1.7321)
  line L3 (1.5, 0.866) -> (1.5, -0.866)
  line L4 (0, 1.7321) -> (1.5, 0.866)
  line L5 (-1.5, 0.866) -> (0, 1.7321)
  line L6 (-1.5, -0.866) -> (-1.5, 0.866)
  circle C1 centre (0, 0) radius 5
  point P1 (0, 0)
  point P9 (0, 0)
  coincident P1 P9
  vertical L6
  dimension "d12" distance L3 L6 = 3
extrude "Extrude1" cut sketch "Sketch2" profile of L1 L2 L3 L4 L5 L6 against normal blind 2

design "circuit_modular_stepper"
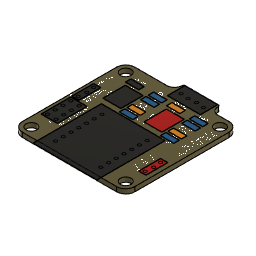
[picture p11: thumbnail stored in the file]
sketch "Outline" plane through (0, 0, 0) normal (0, 0, 1) x axis (1, 0, 0)
  line L1 (35, 1) -> (4, 1)
  line L2 (38, 35) -> (38, 4)
  line L3 (31, 38) -> (35, 38)
  line L4 (17.5, 41) -> (28.5, 41)
  line L5 (4, 38) -> (14.5, 38)
  line L6 (1, 4) -> (1, 35)
  arc A1 centre (4, 4) radius 3 clockwise from (4, 1) to (1, 4)
  arc A2 centre (35, 4) radius 3 clockwise from (38, 4) to (35, 1)
  arc A3 centre (35, 35) radius 3 clockwise from (35, 38) to (38, 35)
  arc A4 centre (31.25, 40.25) radius 2.2638 clockwise from (31, 38) to (29, 40.5)
  arc A5 centre (28.5, 40.5) radius 0.5 clockwise from (28.5, 41) to (29, 40.5)
  arc A6 centre (17.5, 40.5) radius 0.5 clockwise from (17, 40.5) to (17.5, 41)
  arc A7 centre (14.5, 40.5) radius 2.5 clockwise from (17, 40.5) to (14.5, 38)
  arc A8 centre (4, 35) radius 3 clockwise from (1, 35) to (4, 38)
canvas "Canvas1"
canvas "Canvas2"
pcbhole "PCBHole1" HoleDepth 1.606 HoleDiameter 3.5 TipAngle 10313.2
pcbhole "PCBHole2" HoleDepth 1.606 HoleDiameter 3.5 TipAngle 10313.2
pcbhole "PCBHole3" HoleDepth 1.606 HoleDiameter 3.5 TipAngle 10313.2
pcbhole "PCBHole4" HoleDepth 1.606 HoleDiameter 3.5 TipAngle 10313.2
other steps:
pcbextrude "PCBExtrude1"
pcbextrude "PCBExtrude1"
extrude "Extrude1" sketch "Outline" blind 1.5 bodies "Board"
box_primitive "BoxPrimitive1" DistanceX 7.1628 DistanceY 2.3368 DistanceZ 0.1 OffsetDistanceX 0 OffsetDistanceY 0
box_primitive "BoxPrimitive1" DistanceX 10.827 DistanceY 5.727 DistanceZ 0.1 OffsetDistanceX 0 OffsetDistanceY 0
box_primitive "BoxPrimitive1" DistanceX 5.353 DistanceY 9.7028 DistanceZ 0.1 OffsetDistanceX 0 OffsetDistanceY 0
box_primitive "BoxPrimitive1" DistanceX 4.4 DistanceY 1.8 DistanceZ 0.1 OffsetDistanceX 0 OffsetDistanceY 0
box_primitive "BoxPrimitive1" DistanceX 7.35 DistanceY 5.8597 DistanceZ 0.1 OffsetDistanceX 0 OffsetDistanceY 0
box_primitive "BoxPrimitive1" DistanceX 22.4638 DistanceY 20.955 DistanceZ 0.1 OffsetDistanceX 0 OffsetDistanceY 0
pcbextrude "PCBExtrude1"
pcbextrude "PCBExtrude2" bodies "CopperHoles"
create_component "CreateComponent1"
create_component "CreateComponent2"
create_component "CreateComponent3"
create_component "CreateComponent4"
create_component "CreateComponent1"
create_component "CreateComponent2"
create_component "CreateComponent3"
create_component "CreateComponent4"
create_component "CreateComponent5"
create_component "CreateComponent6"
as_built_joint "As-built1"
named bodies: "Board", "CopperHoles"

design "HW_M5x20-SHCS"
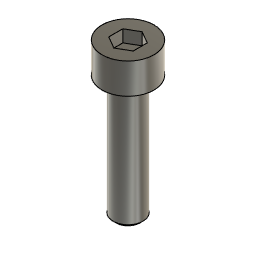
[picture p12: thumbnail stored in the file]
sketch "Sketch1" plane through (0, 0, 0) normal (0, 1, 0) x axis (1, 0, 0)
  line L1 (0, 20) -> (0, -5)
  line L2 (1.95, 20) -> (0, 20)
  line L3 (2.45, 19.5) -> (1.95, 20)
  line L4 (2.45, 0) -> (2.45, 19.5)
  line L5 (4.25, 0) -> (2.45, 0)
  line L6 (4.25, -5) -> (4.25, 0)
  line L7 (0, -5) -> (4.25, -5)
  point P1 (0, 0)
  point P4 (1.95, 20)
  point P5 (2.45, 19.5)
  point P3 (0, 20)
  point P7 (4.25, 0)
  point P8 (4.25, -5)
  point P2 (0, -5)
  vertical L1
  perpendicular L1 L2
  perpendicular L2 L4
  perpendicular L4 L5
  perpendicular L5 L6
  horizontal L7
  coincident P1 L1
  coincident P1 L5
  dimension "d1" distance P1 L2 = 20
  dimension "d2" angle L2 L3 = 45
  dimension "d3" distance P4 P5 = 0.5
  dimension "d4" distance P3 L4 = 2.45 (= "( 4.9 / 2 ) * 1 mm")
  dimension "d5" distance P7 P8 = 5
  dimension "d6" distance P2 P8 = 4.25 (= "( 8.5 / 2 ) * 1 mm")
revolve "Revolve1" sketch "Sketch1" AlongAngle 360
sketch "Sketch2" plane through (0, 0, 5) normal (0, 0, 1) x axis (-1, 0, 0)
  line L1 (0, -2.3094) -> (-2, -1.1547)
  line L2 (2, -1.1547) -> (0, -2.3094)
  line L3 (2, 1.1547) -> (2, -1.1547)
  line L4 (0, 2.3094) -> (2, 1.1547)
  line L5 (-2, 1.1547) -> (0, 2.3094)
  line L6 (-2, -1.1547) -> (-2, 1.1547)
  circle C1 centre (0, 0) radius 4.25
  point P1 (0, 0)
  point P9 (0, 0)
  point P5 (2, -1.1547)
  coincident P1 P9
  vertical L6
  dimension "d8" distance P5 L6 = 4
extrude "Extrude1" cut sketch "Sketch2" profile of L1 L2 L3 L4 L5 L6 against normal blind 2

design "circuit_mount_stepper_simple" references "circuit_modular_stepper"
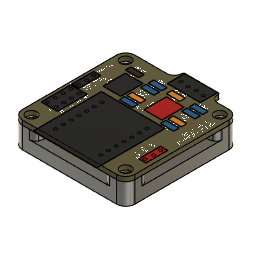
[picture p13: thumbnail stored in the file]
sketch "Sketch1" plane through (0, 0, 0) normal (0, 0, 1) x axis (1, 0, 0)
  line L1 (-18.5, 18.5) -> (18.5, 18.5)
  line L2 (-18.5, -18.5) -> (-18.5, 18.5)
  line L3 (18.5, -18.5) -> (-18.5, -18.5)
  line L4 (18.5, 18.5) -> (18.5, -18.5)
  line L5 (-18.5, -18.5) -> (18.5, 18.5)
  line L6 (18.5, -18.5) -> (-18.5, 18.5)
  line L7 (15.5, 15.5) -> (-15.5, 15.5)
  line L8 (15.5, -15.5) -> (15.5, 15.5)
  line L9 (-15.5, -15.5) -> (15.5, -15.5)
  line L10 (-15.5, 15.5) -> (-15.5, -15.5)
  circle C1 centre (15.5, 15.5) radius 1.7
  circle C2 centre (-15.5, 15.5) radius 1.7
  circle C3 centre (-15.5, -15.5) radius 1.7
  circle C4 centre (15.5, -15.5) radius 1.7
  circle C5 centre (-15.5, 15.5) radius 4.5
  circle C6 centre (15.5, 15.5) radius 4.5
  circle C7 centre (15.5, -15.5) radius 4.5
  circle C8 centre (-15.5, -15.5) radius 4.5
  circle C9 centre (0, 0) radius 15
  circle C10 centre (0, 0) radius 2.5
  circle C11 centre (0, 0) radius 4
  circle C12 centre (0, 0) radius 6.5
  point P6 (0, 0)
  point P1 (0, 0)
  point P9 (15.5, -15.5)
  point P7 (-15.5, 15.5)
  point P8 (15.5, 15.5)
  point P11 (15.5, 15.5)
  point P12 (-15.5, 15.5)
  point P10 (-15.5, -15.5)
  point P13 (-15.5, -15.5)
  point P14 (15.5, -15.5)
  point P19 (0, 0)
  point P21 (0, 0)
  point P2 (18.5, 18.5)
  point P3 (-18.5, 18.5)
  horizontal L1
  perpendicular L1 L2
  parallel L1 L3
  parallel L2 L4
  coincident L5 P6
  coincident L6 P6
  coincident P1 P6
  equal L1 L4
  horizontal L7
  vertical L8
  horizontal L9
  vertical L10
  coincident L6 P9
  coincident L6 P7
  coincident L5 P8
  equal C3 C4
  equal C1 C4
  equal C1 C2
  coincident P8 P11
  coincident P7 P12
  coincident P10 P13
  coincident P9 P14
  concentric C2 C5
  concentric C1 C6
  concentric C4 C7
  concentric C3 C8
  equal C5 C8
  equal C5 C6
  equal C6 C7
  coincident P1 P19
  concentric C9 C10
  coincident P1 P21
  concentric C9 C12
  dimension "d1" distance P7 P8 = 31
  dimension "d2" distance P2 P3 = 37
  dimension "d3" diameter C1 = 3.4
  dimension "d4" distance L4 P11 = 3
  dimension "d5" diameter C6 = 9
  dimension "d6" diameter C9 = 30
  dimension "d7" diameter C10 = 5
  dimension "d8" diameter C11 = 8
  dimension "d9" distance C11 C12 = 2.5
extrude "Extrude1" new body sketch "Sketch1" profile of L1 L2 L3 L4 C1 C2 C3 C4 C5 C6 C7 C8 along normal blind 7 bodies "circuit_mount_stepper_simple"
extrude "Extrude4" add sketch "Sketch1" profile of L1 L2 L3 L4 C5 C6 C7 C8 C9 to an object offset -3
chamfer "Chamfer4" distance 0.5
fillet "Fillet1" radius 3
fillet "Fillet2" radius 2
chamfer "Chamfer5" distance 0.5
component_insert "Component Insert"
joint "Assemble1" alignAngle 0 alignOffsetX 0 alignOffsetY 0 alignOffsetZ 0
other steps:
joint_origin "JointOrigin1"
named bodies: "circuit_mount_stepper_simple"

design "limit_mount" references "PP_SWTC_Omron-V154"
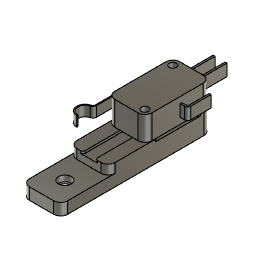
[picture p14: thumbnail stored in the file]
sketch "Sketch1" plane through (0, 0, 0) normal (0, 0, 1) x axis (1, 0, 0)
  line L1 (8.15, -10) -> (-8.15, -10)
  line L2 (8.15, 54.2) -> (8.15, -10)
  line L3 (-8.15, 54.2) -> (8.15, 54.2)
  line L4 (-8.15, -10) -> (-8.15, 54.2)
  line L5 (0, -10) -> (0, 0)
  line L6 (8.15, 10.25) -> (-8.15, 10.25)
  line L7 (-5.15, 29) -> (5.15, 29)
  line L8 (-5.15, 51.2) -> (-5.15, 29)
  line L9 (5.15, 51.2) -> (-5.15, 51.2)
  line L10 (5.15, 29) -> (5.15, 51.2)
  line L11 (0, 0) -> (0, 29)
  line L12 (-2.65, 48.7) -> (-2.65, 54.2)
  line L13 (-8.15, 48.7) -> (-2.65, 48.7)
  line L14 (2.65, 31.5) -> (8.15, 31.5)
  line L15 (2.65, 10.25) -> (2.65, 31.5)
  line L16 (-2.65, 31.5) -> (-8.15, 31.5)
  line L17 (-2.65, 10.25) -> (-2.65, 31.5)
  line L18 (2.65, 48.7) -> (2.65, 54.2)
  line L19 (8.15, 48.7) -> (2.65, 48.7)
  circle C1 centre (0, 0) radius 2.75
  circle C2 centre (-5.15, 51.2) radius 1.35
  circle C3 centre (5.15, 29) radius 1.35
  circle C4 centre (5.15, 29) radius 2.5
  circle C5 centre (-5.15, 51.2) radius 2.5
  circle C6 centre (-5.15, 29) radius 1.35
  circle C7 centre (5.15, 51.2) radius 1.35
  point P1 (0, 0)
  point P2 (0, 0)
  point P7 (0, 0)
  point P8 (0, -10)
  point P9 (-8.15, 10.25)
  point P10 (8.15, 10.25)
  point P13 (-5.15, 51.2)
  point P15 (-5.15, 51.2)
  point P11 (5.15, 29)
  point P16 (5.15, 29)
  point P17 (0, 29)
  point P18 (0, 0)
  point P19 (-2.65, 54.2)
  point P21 (-8.15, 48.7)
  point P22 (8.15, 31.5)
  point P24 (2.65, 10.25)
  point P31 (2.65, 54.2)
  point P20 (-2.65, 48.7)
  point P32 (2.65, 48.7)
  point P33 (8.15, 48.7)
  point P27 (-8.15, 31.5)
  point P23 (2.65, 31.5)
  point P28 (-2.65, 31.5)
  point P29 (-2.65, 10.25)
  point P3 (-8.15, -10)
  point P4 (8.15, -10)
  point P14 (5.15, 51.2)
  point P25 (5.15, 29)
  point P26 (-5.15, 51.2)
  coincident P1 P2
  horizontal L1
  vertical L2
  horizontal L3
  vertical L4
  coincident P1 P7
  midpoint L1 P8
  vertical L5
  coincident L4 P9
  coincident L2 P10
  perpendicular L2 L6
  horizontal L7
  vertical L8
  horizontal L9
  vertical L10
  coincident P13 P15
  coincident P11 P16
  equal C2 C3
  midpoint L7 P17
  coincident P1 P18
  vertical L11
  coincident L3 P19
  perpendicular L3 L12
  coincident L4 P21
  perpendicular L4 L13
  coincident L2 P22
  perpendicular L10 L14
  coincident L6 P24
  perpendicular L6 L15
  concentric C3 C4
  concentric C2 C5
  equal C4 C5
  tangent L12 C5
  tangent L13 C5
  tangent L14 C4
  tangent L15 C4
  symmetric C2 L11 C7
  symmetric C3 L11 C6
  symmetric L11 P19 P31
  symmetric L11 P20 P32
  symmetric L11 P21 P33
  symmetric L11 P22 P27
  symmetric L11 P23 P28
  symmetric L11 P24 P29
  dimension "d1" diameter C1 = 5.5
  dimension "d2" distance P3 P4 = 16.3
  dimension "d3" distance P7 P8 = 10
  dimension "d4" distance P1 L6 = 10.25
  dimension "d5" diameter C2 = 2.7
  dimension "d6" distance P13 P14 = 10.3
  dimension "d7" distance P11 P14 = 22.2
  dimension "d8" distance L2 L10 = 3
  dimension "d9" distance P2 P25 = 29
  dimension "d10" diameter C4 = 5
  dimension "d11" distance L3 P26 = 3
extrude "Extrude1" new body sketch "Sketch1" profile of C1 L1 L2 L3 L4 L6 C2 C3 L12 L13 L14 L15 L16 L17 C6 L18 L19 C7 against normal blind 5 bodies "limit_mount"
extrude "Extrude2" add sketch "Sketch1" profile of L2 L3 L4 L6 C2 C3 L12 L13 L14 L15 L16 L17 C6 L18 L19 C7 along normal blind 4
extrude "Extrude3" add sketch "Sketch1" profile of L2 L3 L4 L6 L12 L13 L14 L15 L16 L17 C6 L18 L19 C7 to an object offset -1
chamfer "Chamfer1" distance 2.5 distance 2.5
fillet "Fillet1" radius 3
fillet "Fillet2" radius 1
chamfer "Chamfer2" distance 0.5
component_insert "Component Insert"
joint "Assemble1" alignAngle -90 alignOffsetX 0 alignOffsetY 0 alignOffsetZ 0
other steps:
joint_origin "JointOrigin1"
named bodies: "limit_mount"

design "HW_M3x50-SHCS"
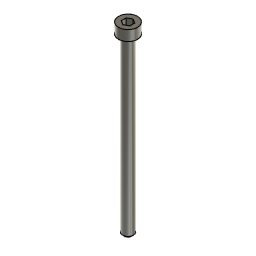
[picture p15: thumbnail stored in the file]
sketch "Sketch1" plane through (0, 0, 0) normal (0, 1, 0) x axis (1, 0, 0)
  line L1 (0, 50) -> (0, -3)
  line L2 (1.05, 50) -> (0, 50)
  line L3 (1.55, 49.5) -> (1.05, 50)
  line L4 (1.55, 0) -> (1.55, 49.5)
  line L5 (2.75, 0) -> (1.55, 0)
  line L6 (2.75, -3) -> (2.75, 0)
  line L7 (0, -3) -> (2.75, -3)
  point P1 (0, 0)
  point P4 (1.05, 50)
  point P5 (1.55, 49.5)
  point P3 (0, 50)
  point P7 (2.75, 0)
  point P8 (2.75, -3)
  point P2 (0, -3)
  vertical L1
  perpendicular L1 L2
  perpendicular L2 L4
  perpendicular L4 L5
  perpendicular L5 L6
  horizontal L7
  coincident P1 L1
  coincident P1 L5
  dimension "d1" distance P1 L2 = 50
  dimension "d2" angle L2 L3 = 45
  dimension "d3" distance P4 P5 = 0.5
  dimension "d4" distance P3 L4 = 1.55 (= "( 3.1 / 2 ) * 1 mm")
  dimension "d5" distance P7 P8 = 3
  dimension "d6" distance P2 P8 = 2.75 (= "( 5.5 / 2 ) * 1 mm")
revolve "Revolve1" sketch "Sketch1" AlongAngle 360
sketch "Sketch2" plane through (0, 0, 3) normal (0, 0, 1) x axis (-1, 0, 0)
  line L1 (0, -1.4434) -> (-1.25, -0.7217)
  line L2 (1.25, -0.7217) -> (0, -1.4434)
  line L3 (1.25, 0.7217) -> (1.25, -0.7217)
  line L4 (0, 1.4434) -> (1.25, 0.7217)
  line L5 (-1.25, 0.7217) -> (0, 1.4434)
  line L6 (-1.25, -0.7217) -> (-1.25, 0.7217)
  circle C1 centre (0, 0) radius 2.75
  point P1 (0, 0)
  point P9 (0, 0)
  point P5 (1.25, -0.7217)
  coincident P1 P9
  vertical L6
  dimension "d8" distance P5 L6 = 2.5
extrude "Extrude1" cut sketch "Sketch2" profile of L1 L2 L3 L4 L5 L6 against normal blind 2

design "PP_SWTC_Omron-V154"
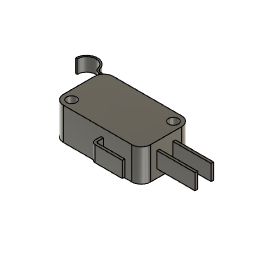
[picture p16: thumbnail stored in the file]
sketch "Sketch1" plane through (0, 0, 0) normal (0, 0, 1) x axis (1, 0, 0)
  line L1 (22.2, 0) -> (0, 0)
  line L2 (22.2, 10.3) -> (22.2, 0)
  line L3 (0, 10.3) -> (22.2, 10.3)
  line L4 (0, 0) -> (0, 10.3)
  line L5 (25, -2.8) -> (-2.8, -2.8)
  line L6 (25, 13.1) -> (25, -2.8)
  line L7 (-2.8, 13.1) -> (25, 13.1)
  line L8 (-2.8, -2.8) -> (-2.8, 13.1)
  line L9 (14.1, 15.2) -> (14.1, 13.1)
  line L10 (-6.9, 15.2) -> (14.1, 15.2)
  line L11 (13.6, 14.7) -> (-7.442, 14.7)
  line L12 (13.6, 13.1) -> (13.6, 14.7)
  line L13 (-13.9, 15.2) -> (-13.4, 15.2)
  line L14 (-10.4, 18.7) -> (-10.4, 15.2)
  line L15 (37.2, 8.1) -> (25, 8.1)
  line L16 (37.2, 7.3) -> (37.2, 8.1)
  line L17 (25, 7.3) -> (37.2, 7.3)
  line L18 (25, 8.1) -> (25, 7.3)
  line L19 (37.2, 3) -> (25, 3)
  line L20 (37.2, 2.2) -> (37.2, 3)
  line L21 (25, 2.2) -> (37.2, 2.2)
  line L22 (25, 3) -> (25, 2.2)
  line L23 (13, -5.2) -> (13, -2.8)
  line L24 (22.2, -5.2) -> (13, -5.2)
  line L25 (22.2, -6) -> (22.2, -5.2)
  line L26 (12.2, -6) -> (22.2, -6)
  line L27 (12.2, -2.8) -> (12.2, -6)
  circle C1 centre (0, 0) radius 2.8
  circle C2 centre (22.2, 10.3) radius 2.8
  circle C3 centre (22.2, 10.3) radius 1.55
  circle C4 centre (0, 0) radius 1.55
  arc A1 centre (-10.4, 15.2) radius 3.5 clockwise from (-13.9, 15.2) to (-6.9, 15.2)
  arc A2 centre (-10.4, 15.2) radius 3 clockwise from (-13.4, 15.2) to (-7.442, 14.7)
  point P1 (0, 0)
  point P2 (0, 0)
  point P10 (0, 0)
  point P4 (22.2, 10.3)
  point P11 (22.2, 10.3)
  point P13 (0, 0)
  point P14 (14.1, 13.1)
  point P18 (-13.9, 15.2)
  point P17 (-10.4, 15.2)
  point P19 (-10.4, 15.2)
  point P23 (13.6, 13.1)
  point P24 (-10.4, 15.2)
  point P25 (-10.4, 18.7)
  point P26 (25, 8.1)
  point P30 (25, 3)
  point P34 (13, -2.8)
  point P39 (12.2, -2.8)
  point P31 (37.2, 3)
  point P3 (22.2, 0)
  point P6 (-2.8, -2.8)
  point P7 (25, -2.8)
  point P9 (-2.8, 13.1)
  point P8 (25, 13.1)
  point P12 (22.2, 10.3)
  point P22 (13.6, 14.7)
  point P15 (14.1, 15.2)
  point P35 (13, -5.2)
  point P32 (37.2, 2.2)
  point P27 (37.2, 8.1)
  point P28 (37.2, 7.3)
  point P37 (22.2, -6)
  horizontal L1
  vertical L2
  horizontal L3
  vertical L4
  coincident P1 P2
  horizontal L5
  vertical L6
  horizontal L7
  vertical L8
  coincident P1 P10
  coincident P4 P11
  concentric C2 C3
  coincident P1 P13
  equal C3 C4
  tangent L7 C2
  tangent L6 C2
  tangent L5 C1
  coincident L7 P14
  perpendicular L7 L9
  perpendicular L9 L10
  coincident L10 P18
  coincident P17 P19
  horizontal L11
  coincident L7 P23
  perpendicular L7 L12
  coincident P19 L13
  horizontal L13
  coincident P19 P24
  midpoint A1 P25
  horizontal L15
  vertical L16
  horizontal L17
  vertical L18
  coincident L6 P26
  horizontal L19
  vertical L20
  horizontal L21
  vertical L22
  coincident L6 P30
  coincident L5 P34
  perpendicular L5 L23
  perpendicular L6 L24
  perpendicular L24 L25
  perpendicular L25 L26
  coincident L5 P39
  perpendicular L5 L27
  coincident L16 P31
  dimension "d2" distance P2 P3 = 22.2
  dimension "d3" distance P3 P4 = 10.3
  dimension "d4" distance P6 P7 = 27.8
  dimension "d5" distance P6 P9 = 15.9
  dimension "d6" diameter C3 = 3.1
  dimension "d7" distance P8 P12 = 2.8
  dimension "d8" distance L9 L12 = 0.5
  dimension "d9" distance L10 P22 = 0.5 (= "d8")
  dimension "d10" distance A1 A2 = 0.5 (= "d8")
  dimension "d11" radius A1 = 3.5
  dimension "d12" distance P10 P25 = 18.7
  dimension "d13" distance P12 P25 = 32.6
  dimension "d14" distance P12 P15 = 8.1
  dimension "d25" distance P35 L27 = 0.8
  dimension "d26" distance P35 L26 = 0.8 (= "d25")
  dimension "d27" distance P31 P32 = 0.8 (= "d25")
  dimension "d28" distance P27 P28 = 0.8 (= "d25")
  dimension "d29" distance P8 P37 = 19.1
  dimension "d30" distance P7 P37 = 2.8
  dimension "d31" distance P7 L23 = 12
  dimension "d33" distance P8 P27 = 5
  dimension "d34" distance P6 P28 = 40
  dimension "d35" distance P7 P32 = 5 (= "d33")
extrude "Extrude1" new body sketch "Sketch1" profile of L5 L6 L7 L8 C3 C4 distance 10.3
extrude "Extrude2" add sketch "Sketch1" profile of L7 L9 L10 A1 A2 L11 L12 L13 distance 4.3
fillet "Fillet1" radius 3
fillet "Fillet2" radius 1
fillet "Fillet3" radius 1.5
extrude "Extrude3" add sketch "Sketch1" profile of L5 L6 L15 L16 L17 L18 L19 L20 L21 L22 L23 L24 L25 L26 L27 distance 5
fillet "Fillet4" radius 0.5
fillet "Fillet5" radius 1.3 (= "0.5 mm + 0.8 mm")

design "HW_M3-Washer"
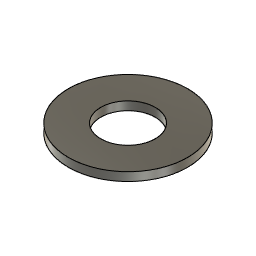
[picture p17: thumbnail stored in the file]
sketch "Sketch1" plane through (0, 0, 0) normal (0, 1, 0) x axis (1, 0, 0)
  line L1 (3.5, 0) -> (1.6, 0)
  line L2 (3.5, -0.5) -> (3.5, 0)
  line L3 (1.6, -0.5) -> (3.5, -0.5)
  line L4 (1.6, 0) -> (1.6, -0.5)
  point P1 (0, 0)
  point P2 (1.6, 0)
  point P5 (1.6, -0.5)
  horizontal L1
  vertical L2
  horizontal L3
  vertical L4
  coincident P1 L1
  dimension "d1" distance P2 P5 = 0.5
  dimension "d2" distance P1 L4 = 1.6 (= "( 3.2 / 2 ) * 1 mm")
  dimension "d3" distance P1 L2 = 3.5 (= "( 7 / 2 ) * 1 mm")
revolve "Revolve1" sketch "Sketch1" AlongAngle 360

design "PP_TRNS_GT2-Pulley-20T-6mm"
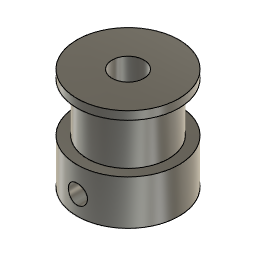
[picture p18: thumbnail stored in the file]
